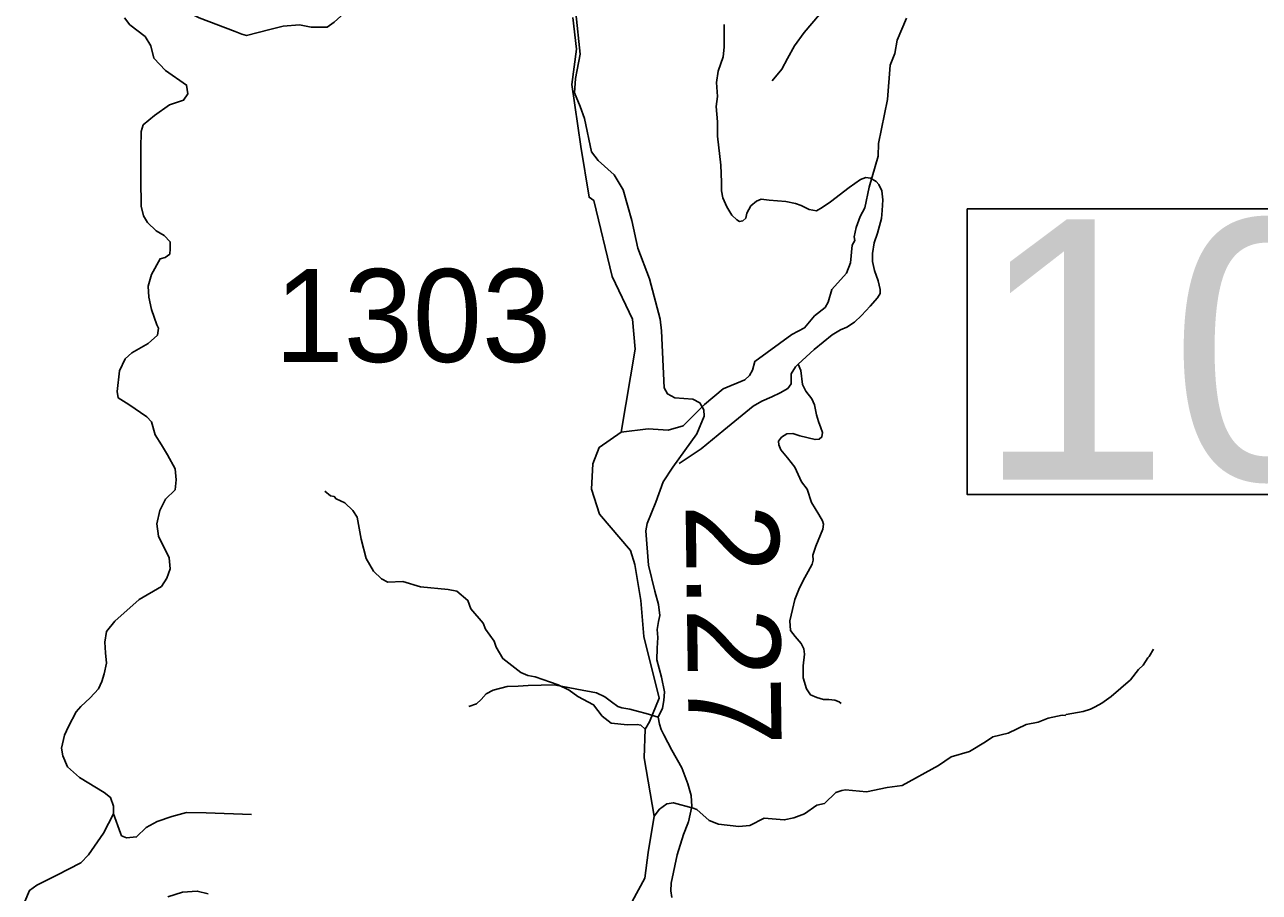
# Model space of a CAD drawing. Extents: x 1248089 to 1457196, y 820910 to 988753.
# Drawn here: x 1294097 to 1300740, y 896327 to 900992 of the extents above; entities that cross this region are included whole.
import ezdxf

# ---------------------------------------------------------------- set-up
doc = ezdxf.new("R2010")
doc.units = 0
for name, color, linetype in [('Exist Hydrographic Creek Single Shore', 7, 'Continuous'), ('Exist Hydrographic Misc Water Feature', 7, 'Continuous'), ('Exist Road Non-System Type 51', 7, 'Continuous'), ('Exist Road Secondary Structure Standard Bridge Number Label', 7, 'Continuous'), ('Exist Road Secondary Type 51 Attributed', 7, 'Continuous'), ('Prop GRAU CAT1 Cell', 7, 'Continuous'), ('Prop Lane Lines', 7, 'Continuous')]:
    doc.layers.add(name, color=color, linetype=linetype)

msp = doc.modelspace()

# ---------------------------------------------------------------- linework, layer by layer
at = {"layer": 'Exist Hydrographic Creek Single Shore'}
msp.add_lwpolyline([(1297366.2, 896276.8), (1297433.4, 896403.5), (1297451.4, 896540.4), (1297485, 896736.9), (1297430.8, 897049.6), (1297435.6, 897204.6), (1297459.2, 897243.4), (1297510.8, 897370), (1297428.2, 897701.6), (1297412.7, 897895.5), (1297379.9, 898089.8), (1297356.9, 898165.7), (1297190.7, 898359.8), (1297146.8, 898494.2), (1297154.6, 898631.2), (1297188.1, 898719), (1297306.6, 898801), (1297381.6, 899248.4), (1297368.5, 899409.5), (1297257.5, 899638.2), (1297159.5, 900047.3), (1297134.5, 900064.2), (1297090, 900336.6), (1297041, 900671.5), (1297066.8, 900860.2), (1297046.2, 901030.7)], dxfattribs=at)
at = {"layer": 'Exist Hydrographic Misc Water Feature'}
for points in [[(1298842.3, 901027.2), (1298791.5, 900908.3), (1298779.7, 900838), (1298754.2, 900774.5), (1298739.6, 900590.9), (1298691.8, 900353.9), (1298690.1, 900285.8), (1298642, 900119.3), (1298617.2, 900007.4), (1298592.1, 899960.3), (1298570.6, 899902.4), (1298561.3, 899851), (1298564.8, 899831.2), (1298550.2, 899806.9), (1298540, 899711), (1298518.6, 899655.7), (1298440.3, 899567.8), (1298420.7, 899500), (1298403.9, 899472.4), (1298346.8, 899426), (1298293.2, 899363.1), (1298224.3, 899326.7), (1298026.5, 899181.3), (1298013.4, 899133.9), (1297996.7, 899106.4), (1297972, 899083.1), (1297854.8, 899033.7), (1297754.6, 898950.4), (1297639.7, 898834.5), (1297559.1, 898812.3), (1297451.3, 898819.4), (1297306.6, 898801)], [(1295711.8, 898484.1), (1295743.2, 898458.9), (1295763.1, 898454.4), (1295772.8, 898441.9), (1295820.3, 898421.2), (1295863.3, 898380.1), (1295886.4, 898343.5), (1295907.6, 898226.7), (1295935, 898121.9), (1295973.4, 898053), (1296016.4, 898011.9), (1296052, 897994.7), (1296132.3, 897998.8), (1296227.5, 897969), (1296375.4, 897955.4), (1296423.1, 897946.2), (1296482, 897896.6), (1296498.8, 897852), (1296564.9, 897774.3), (1296576.2, 897742.1), (1296622.7, 897677.1), (1296633.8, 897644.9), (1296670.4, 897583.5), (1296766.7, 897509.3), (1296804.3, 897492.2), (1296844.1, 897485.6), (1296967.1, 897442.1), (1297026.4, 897413), (1297073.7, 897379.3), (1297158.7, 897335.7), (1297205.1, 897274), (1297252.3, 897237), (1297340.1, 897227), (1297392.2, 897230), (1297412.1, 897225.5), (1297435.6, 897204.6)], [(1299267.3, 897135.8), (1299307.4, 897162.8), (1299388.4, 897182.9), (1299486, 897229.4), (1299550.5, 897242.6), (1299605, 897263), (1299679.6, 897278.8), (1299695.6, 897278.4), (1299701.6, 897282.2), (1299792.1, 897299.6), (1299832.5, 897312.4), (1299856.8, 897323.7), (1299893.4, 897344.6), (1299942.4, 897379.2), (1300047, 897470.1), (1300090.6, 897524.9), (1300115.3, 897548.1), (1300140.4, 897587.4), (1300148.6, 897595.2), (1300171.7, 897634.5)], [(1299267.3, 897135.8), (1299181.9, 897083.4), (1299083.2, 897055.8), (1299014, 897009.6), (1298819.2, 896900.3), (1298738.9, 896890.3), (1298626.1, 896867.2), (1298514.4, 896877.6), (1298494.3, 896874.7), (1298462, 896863.1), (1298400.6, 896804.4), (1298360.3, 896795.4), (1298293, 896749), (1298236.5, 896726.4), (1298184.1, 896716), (1298076.3, 896724.7), (1297999.3, 896686), (1297939.2, 896679.8), (1297831.4, 896692.7), (1297779.8, 896713.5), (1297713.1, 896771.4), (1297693.4, 896780), (1297588, 896808.4), (1297551.8, 896801.7), (1297513.2, 896774.6), (1297485, 896736.9)]]:
    msp.add_lwpolyline(points, dxfattribs=at)
at = {"layer": 'Exist Road Non-System Type 51'}
for points in [[(1298599.1, 901413.9), (1298576.2, 901324.8), (1298547.9, 901264.8), (1298472, 901165.4), (1298373.1, 901047.2), (1298291.9, 900949.6), (1298238.9, 900879.3), (1298201.8, 900810.8), (1298171.8, 900752.5), (1298119.7, 900690)], [(1294755.5, 901331.1), (1294837.3, 901236.7), (1294897.1, 901139.1), (1294938, 901079.2), (1295035.5, 901028.9), (1295230.6, 900956.4), (1295265.2, 900940.7), (1295290.4, 900934.4), (1295416.2, 900965.9), (1295488.6, 900984.8), (1295576.7, 900991.1), (1295639.6, 900978.5), (1295724.6, 900978.5), (1295762.3, 901006.8), (1295815.8, 901054), (1295859.9, 901107.6), (1295885.1, 901148.5)], [(1294634.7, 901030), (1294663.1, 900992.2), (1294744.9, 900929.2), (1294776.3, 900878.8), (1294792.1, 900812.7), (1294855, 900746.5), (1294968.3, 900667.8), (1294974.6, 900620.6), (1294952.6, 900585.9), (1294877, 900560.7), (1294795.2, 900504), (1294735.4, 900453.6), (1294723.6, 900418.2), (1294722.1, 900328.5), (1294722.1, 900125.3), (1294723.6, 900052.9), (1294723.6, 900016.7), (1294736.2, 899964.7), (1294758.3, 899928.5), (1294805.5, 899884.4), (1294847.9, 899859.2), (1294881, 899824.6), (1294881, 899786.8), (1294877.8, 899758.5), (1294852.7, 899739.6), (1294825.9, 899733.3), (1294780.3, 899649.8), (1294761.4, 899586.8), (1294764.5, 899527), (1294780.3, 899460.9), (1294808.6, 899379), (1294818, 899360.1), (1294811.7, 899322.3), (1294761.4, 899278.2), (1294673.3, 899227.8), (1294638.7, 899196.3), (1294607.2, 899130.2), (1294594.6, 899020), (1294600.9, 898985.3), (1294657.6, 898950.7), (1294755.1, 898884.5), (1294780.3, 898856.2), (1294799.2, 898786.9), (1294833.8, 898733.4), (1294865.2, 898679.8), (1294906.2, 898604.3), (1294912.4, 898544.4), (1294906.2, 898490.9), (1294855.8, 898440.5), (1294824.3, 898380.7), (1294808.6, 898308.2), (1294818, 898242.1), (1294874.7, 898125.6), (1294881, 898065.7), (1294862.1, 898015.4), (1294833.8, 897971.3), (1294714.2, 897902), (1294582, 897785.5), (1294538, 897728.8), (1294528.5, 897672.1), (1294531.7, 897615.4), (1294538, 897558.7), (1294525.4, 897502), (1294512.8, 897461.1), (1294493.9, 897420.2), (1294449.9, 897372.9), (1294399.5, 897325.7), (1294374.3, 897297.3), (1294333.4, 897218.6), (1294311.4, 897171.4), (1294295.7, 897102.1), (1294302, 897061.1), (1294327.1, 897001.3), (1294393.2, 896944.6), (1294525.4, 896862.7), (1294560, 896837.5), (1294575.7, 896790.3), (1294575.7, 896749.4)], [(1298258.3, 899167.7), (1298344.8, 899246.6), (1298442, 899325.4), (1298486.1, 899351.1), (1298521.4, 899366.5), (1298562, 899392.2), (1298599.1, 899428.2), (1298646.8, 899479.6), (1298686.5, 899523.3), (1298700.6, 899547.2), (1298700.6, 899567.8), (1298690.1, 899615.8), (1298670.6, 899670.6), (1298658.3, 899718.6), (1298658.3, 899761.4), (1298668.9, 899819.6), (1298685.6, 899871.9), (1298696.2, 899911.3), (1298706.8, 899950.7), (1298710.4, 899993.5), (1298713.9, 900050.1), (1298708.6, 900098.1), (1298692.7, 900132.3), (1298678.6, 900149.5), (1298648.6, 900166.6), (1298623.8, 900170), (1298593.8, 900159.7), (1298533.8, 900116.9), (1298433.1, 900039.8), (1298389, 900009), (1298357.2, 899991.8), (1298318.4, 899998.7), (1298276, 900021), (1298244.2, 900031.2), (1298193, 900041.5), (1298102.9, 900048.4), (1298060.6, 900053.5), (1298034.1, 900043.2), (1298004, 900017.5), (1297982.9, 899978.1), (1297977.6, 899952.4), (1297960.8, 899937.9), (1297943.1, 899934.4), (1297929, 899943), (1297902.5, 899968.7), (1297876, 900013.2), (1297853.1, 900061.2), (1297846, 900098.9), (1297846, 900145.2), (1297842.5, 900237.7), (1297825.7, 900392.7), (1297825.7, 900469.8), (1297818.6, 900552.1), (1297825.7, 900606.9), (1297820.4, 900682.3), (1297829.2, 900742.2), (1297855.7, 900819.3), (1297861.9, 900871.6), (1297861.9, 900993.2)], [(1297618.2, 898632.3), (1297736.5, 898711.2), (1297858.4, 898812.2), (1298017.3, 898940.7), (1298063.2, 898968.1), (1298117.9, 898990.4), (1298162.1, 899012.7), (1298202.7, 899036.7), (1298222.1, 899060.7), (1298221.2, 899114.6), (1298244.2, 899152.3), (1298258.3, 899167.7)], [(1298258.3, 899167.7), (1298274.2, 899133.5), (1298283, 899058.1), (1298300.7, 899022.1), (1298332.5, 898981), (1298346.6, 898948.4), (1298357.2, 898893.6), (1298367.8, 898859.4), (1298381.9, 898825.1), (1298390.8, 898799.4), (1298387.2, 898775.4), (1298371.3, 898763.4), (1298350.1, 898761.7), (1298268.9, 898782.3), (1298230.1, 898794.3), (1298198.3, 898792.5), (1298170, 898773.7), (1298154.1, 898753.1), (1298155.9, 898732.6), (1298166.5, 898706.9), (1298201.8, 898664), (1298240.7, 898612.6), (1298276.9, 898534.7), (1298306.9, 898495.3), (1298331.6, 898423.3), (1298370.4, 898358.2), (1298389.9, 898324), (1298395.2, 898306.8), (1298391.6, 898279.4), (1298354.6, 898188.6), (1298337.8, 898139.8), (1298339.5, 898112.4), (1298334.2, 898091.8), (1298313.1, 898052.4), (1298286.6, 898002.7), (1298263.6, 897954.7), (1298240.7, 897901.6), (1298228.3, 897846.8), (1298214.2, 897786.8), (1298218.6, 897734.6), (1298243.3, 897702), (1298275.1, 897664.3), (1298289.2, 897635.2), (1298292.8, 897607.8), (1298285.7, 897544.4), (1298285.7, 897481), (1298303.3, 897421.1), (1298326.3, 897388.5), (1298359.9, 897374.8), (1298395.2, 897362.8), (1298423.4, 897362.8), (1298457, 897359.4), (1298479.9, 897350.8), (1298490.7, 897342.7)], [(1296486.4, 897326.8), (1296528.7, 897340.5), (1296553.5, 897362.8), (1296580, 897393.6), (1296618.8, 897414.2), (1296693, 897433.1), (1296753, 897434.8), (1296806, 897438.2), (1296947.2, 897443.3), (1297069.1, 897419.3), (1297173.3, 897398.8), (1297219.2, 897378.2), (1297254.5, 897350.8), (1297288, 897326.8), (1297311, 897318.3), (1297353.4, 897311.4), (1297399.3, 897299.4), (1297441.6, 897289.1), (1297505.2, 897268.6)], [(1294575.7, 896749.4), (1294522.2, 896645.4), (1294440.4, 896528.9), (1294399.5, 896484.8), (1294270.5, 896418.7), (1294163.5, 896365.2), (1294122.6, 896336.8), (1294097.4, 896277)], [(1294575.7, 896749.4), (1294612.1, 896644.2), (1294618.6, 896631.2), (1294644.8, 896620.2), (1294699.2, 896624.6), (1294751.5, 896674.8), (1294810.4, 896707.5), (1294888.8, 896733.7), (1294967.3, 896755.5), (1295074, 896753.3), (1295318.1, 896744.6)], [(1294868.4, 896302.2), (1294947.1, 896327.4), (1295025.7, 896333.7), (1295085.5, 896317.9)]]:
    msp.add_lwpolyline(points, dxfattribs=at)
at = {"layer": 'Exist Road Secondary Structure Standard Bridge Number Label'}
msp.add_lwpolyline([(1299168.9, 900002.2), (1302884.8, 900002.2), (1302884.8, 898465.8), (1299168.9, 898465.8)], close=True, dxfattribs=at)
at = {"layer": 'Exist Road Secondary Type 51 Attributed'}
msp.add_lwpolyline([(1297580.3, 896299.7), (1297573.2, 896334), (1297575, 896375.1), (1297608.5, 896527.6), (1297642.9, 896638.1), (1297665.6, 896697.6), (1297667, 896701.4), (1297668.5, 896705.1), (1297687.1, 896788.9), (1297683.6, 896847.1), (1297665.9, 896910.5), (1297634.1, 896996.2), (1297580.3, 897091.3), (1297536.1, 897173.5), (1297522.9, 897202.6), (1297512.3, 897231.7), (1297505.2, 897268.6), (1297529.1, 897317.4), (1297536.1, 897358.5), (1297539.7, 897404.8), (1297523.8, 897483.6), (1297499, 897577.8), (1297500.8, 897639.5), (1297504.3, 897697.8), (1297500.8, 897740.6), (1297507.9, 897783.4), (1297514.9, 897816), (1297507.9, 897874.2), (1297487.9, 897945.7), (1297453, 898086.7), (1297439.5, 898271), (1297447.2, 898309.4), (1297493.7, 898423.9), (1297532.5, 898534.5), (1297584.7, 898613.5), (1297714.6, 898792), (1297753.4, 898886.6), (1297751.4, 898921.5), (1297730.1, 898958.4), (1297693.3, 898977.8), (1297596.3, 898985.5), (1297555.6, 899006.9), (1297538.2, 899039.9), (1297524.6, 899346.4), (1297516.9, 899408), (1297458.7, 899625.3), (1297397, 899791.3), (1297364, 899938.8), (1297317.5, 900103.7), (1297269.2, 900184.4), (1297183.9, 900262), (1297147.1, 900308.6), (1297110.2, 900487.1), (1297087, 900553), (1297056, 900626.8), (1297061.8, 900703.2), (1297087, 900833.2), (1297063.7, 901056.3)], dxfattribs=at)

# ---------------------------------------------------------------- texts
at = {"layer": 'Exist Road Secondary Structure Standard Bridge Number Label'}
msp.add_text('105', height=1400, dxfattribs=at).set_placement((1299219.1, 898544.9))
at = {"layer": 'Prop GRAU CAT1 Cell'}
msp.add_text('2.27', height=500, rotation=270.75708, dxfattribs=at).set_placement((1297653.3, 898412.2))
at = {"layer": 'Prop Lane Lines'}
msp.add_text('1303', height=500, dxfattribs=at).set_placement((1295442.3, 899178.7))

doc.saveas('drawing.dxf')
